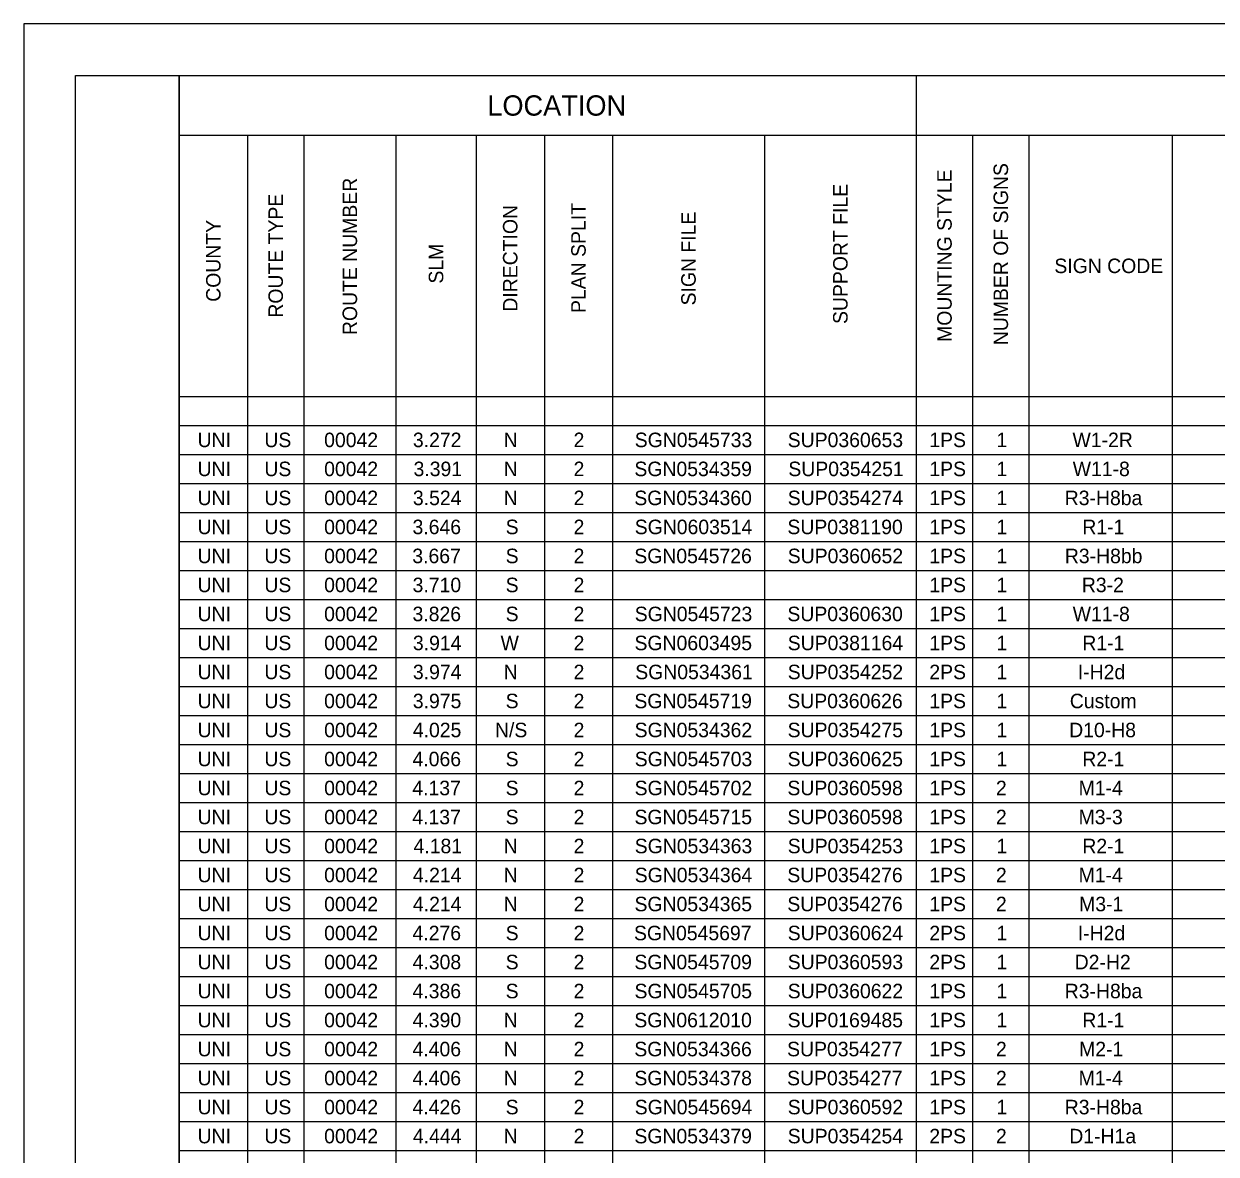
# Model space of a CAD drawing. Extents: x 0 to 34, y 0 to 22.
# Drawn here: x 0 to 11.51, y 11.09 to 22 of the extents above; entities that cross this region are included whole.
import ezdxf

# ---------------------------------------------------------------- set-up
doc = ezdxf.new("R2010")
doc.units = 0
for name, color, linetype in [('SH_Border', 7, 'Continuous'), ('SH_Cut_Line', 7, 'Continuous'), ('SH_Data', 7, 'Continuous'), ('SH_Text', 7, 'Continuous')]:
    doc.layers.add(name, color=color, linetype=linetype)

msp = doc.modelspace()

# ---------------------------------------------------------------- linework, layer by layer
at = {"layer": 'SH_Border'}
for points in [[(0.5, 21.5), (1.5, 21.5), (1.5, 0.5), (0.5, 0.5)], [(1.5, 21.5), (33.5, 21.5), (33.5, 0.5), (1.5, 0.5)]]:
    msp.add_lwpolyline(points, close=True, dxfattribs=at)
at = {"layer": 'SH_Cut_Line'}
msp.add_lwpolyline([(0, 0), (34, 0), (34, 22), (0, 22)], close=True, dxfattribs=at)
at = {"layer": 'SH_Data'}
for p, q in [((1.5, 21.5), (32.004, 21.5)), ((8.615, 21.5), (8.615, 0.764)), ((1.5, 20.924), (28.232, 20.924)), ((1.5, 20.924), (1.5, 0.764)), ((2.159, 20.924), (2.159, 0.764)), ((2.702, 20.924), (2.702, 0.764)), ((3.592, 20.924), (3.592, 0.764)), ((4.366, 20.924), (4.366, 0.764)), ((5.025, 20.924), (5.025, 0.764)), ((5.684, 20.924), (5.684, 0.764)), ((7.149, 20.924), (7.149, 0.764)), ((9.159, 20.924), (9.159, 0.764)), ((9.702, 20.924), (9.702, 0.764)), ((11.086, 20.924), (11.086, 0.764)), ((1.5, 18.404), (32.004, 18.404)), ((1.5, 18.124), (32.004, 18.124)), ((1.5, 17.844), (32.004, 17.844)), ((1.5, 17.564), (32.004, 17.564)), ((1.5, 17.284), (32.004, 17.284)), ((1.5, 17.004), (32.004, 17.004)), ((1.5, 16.724), (32.004, 16.724)), ((1.5, 16.444), (32.004, 16.444)), ((1.5, 16.164), (32.004, 16.164)), ((1.5, 15.884), (32.004, 15.884)), ((1.5, 15.604), (32.004, 15.604)), ((1.5, 15.324), (32.004, 15.324)), ((1.5, 15.044), (32.004, 15.044)), ((1.5, 14.764), (32.004, 14.764)), ((1.5, 14.484), (32.004, 14.484)), ((1.5, 14.204), (32.004, 14.204)), ((1.5, 13.924), (32.004, 13.924)), ((1.5, 13.644), (32.004, 13.644)), ((1.5, 13.364), (32.004, 13.364)), ((1.5, 13.084), (32.004, 13.084)), ((1.5, 12.804), (32.004, 12.804)), ((1.5, 12.524), (32.004, 12.524)), ((1.5, 12.244), (32.004, 12.244)), ((1.5, 11.964), (32.004, 11.964)), ((1.5, 11.684), (32.004, 11.684)), ((1.5, 11.404), (32.004, 11.404)), ((1.5, 11.124), (32.004, 11.124))]:
    msp.add_line(p, q, dxfattribs=at)

# ---------------------------------------------------------------- texts
at = {"layer": 'SH_Text'}
for s, height, p in [('LOCATION', 0.196, (4.474, 21.114)), ('SIGN CODE', 0.14, (9.948, 19.594)), ('UNI', 0.14, (1.677, 17.914)), ('US', 0.14, (2.322, 17.914)), ('00042', 0.14, (2.899, 17.914)), ('3.272', 0.14, (3.756, 17.914)), ('N', 0.14, (4.632, 17.914)), ('2', 0.14, (5.307, 17.914)), ('SGN0545733', 0.14, (5.897, 17.914)), ('SUP0360653', 0.14, (7.374, 17.914)), ('1PS', 0.14, (8.741, 17.914)), ('1', 0.14, (9.389, 17.914)), ('W1-2R', 0.14, (10.123, 17.914)), ('UNI', 0.14, (1.677, 17.634)), ('US', 0.14, (2.322, 17.634)), ('00042', 0.14, (2.899, 17.634)), ('3.391', 0.14, (3.762, 17.634)), ('N', 0.14, (4.632, 17.634)), ('2', 0.14, (5.307, 17.634)), ('SGN0534359', 0.14, (5.894, 17.634)), ('SUP0354251', 0.14, (7.38, 17.634)), ('1PS', 0.14, (8.741, 17.634)), ('1', 0.14, (9.389, 17.634)), ('W11-8', 0.14, (10.125, 17.634)), ('US', 0.14, (2.322, 17.354)), ('00042', 0.14, (2.899, 17.354)), ('3.524', 0.14, (3.756, 17.354)), ('2', 0.14, (5.307, 17.354)), ('SGN0534360', 0.14, (5.893, 17.354)), ('SUP0354274', 0.14, (7.374, 17.354)), ('1PS', 0.14, (8.741, 17.354)), ('R3-H8ba', 0.14, (10.048, 17.354)), ('UNI', 0.14, (1.677, 17.354)), ('N', 0.14, (4.632, 17.354)), ('1', 0.14, (9.389, 17.354)), ('UNI', 0.14, (1.677, 17.074)), ('US', 0.14, (2.322, 17.074)), ('00042', 0.14, (2.899, 17.074)), ('3.646', 0.14, (3.752, 17.074)), ('S', 0.14, (4.651, 17.074)), ('2', 0.14, (5.307, 17.074)), ('SGN0603514', 0.14, (5.897, 17.074)), ('SUP0381190', 0.14, (7.371, 17.074)), ('1PS', 0.14, (8.741, 17.074)), ('1', 0.14, (9.389, 17.074)), ('R1-1', 0.14, (10.218, 17.074)), ('UNI', 0.14, (1.677, 16.794)), ('US', 0.14, (2.322, 16.794)), ('00042', 0.14, (2.899, 16.794)), ('3.667', 0.14, (3.75, 16.794)), ('S', 0.14, (4.651, 16.794)), ('2', 0.14, (5.307, 16.794)), ('SGN0545726', 0.14, (5.893, 16.794)), ('SUP0360652', 0.14, (7.374, 16.794)), ('1PS', 0.14, (8.741, 16.794)), ('1', 0.14, (9.389, 16.794)), ('R3-H8bb', 0.14, (10.049, 16.794)), ('UNI', 0.14, (1.677, 16.514)), ('US', 0.14, (2.322, 16.514)), ('00042', 0.14, (2.899, 16.514)), ('3.710', 0.14, (3.753, 16.514)), ('S', 0.14, (4.651, 16.514)), ('2', 0.14, (5.307, 16.514)), ('1PS', 0.14, (8.741, 16.514)), ('1', 0.14, (9.389, 16.514)), ('R3-2', 0.14, (10.213, 16.514)), ('UNI', 0.14, (1.677, 16.234)), ('US', 0.14, (2.322, 16.234)), ('00042', 0.14, (2.899, 16.234)), ('3.826', 0.14, (3.752, 16.234)), ('S', 0.14, (4.651, 16.234)), ('2', 0.14, (5.307, 16.234)), ('SGN0545723', 0.14, (5.897, 16.234)), ('SUP0360630', 0.14, (7.371, 16.234)), ('1PS', 0.14, (8.741, 16.234)), ('1', 0.14, (9.389, 16.234)), ('W11-8', 0.14, (10.125, 16.234)), ('UNI', 0.14, (1.677, 15.954)), ('US', 0.14, (2.322, 15.954)), ('00042', 0.14, (2.899, 15.954)), ('3.914', 0.14, (3.756, 15.954)), ('W', 0.14, (4.602, 15.954)), ('2', 0.14, (5.307, 15.954)), ('SGN0603495', 0.14, (5.895, 15.954)), ('SUP0381164', 0.14, (7.374, 15.954)), ('1PS', 0.14, (8.741, 15.954)), ('1', 0.14, (9.389, 15.954)), ('R1-1', 0.14, (10.218, 15.954)), ('UNI', 0.14, (1.677, 15.674)), ('US', 0.14, (2.322, 15.674)), ('00042', 0.14, (2.899, 15.674)), ('3.974', 0.14, (3.756, 15.674)), ('N', 0.14, (4.632, 15.674)), ('2', 0.14, (5.307, 15.674)), ('SGN0534361', 0.14, (5.902, 15.674)), ('SUP0354252', 0.14, (7.374, 15.674)), ('2PS', 0.14, (8.741, 15.674)), ('1', 0.14, (9.389, 15.674)), ('I-H2d', 0.14, (10.174, 15.674)), ('UNI', 0.14, (1.677, 15.394)), ('US', 0.14, (2.322, 15.394)), ('00042', 0.14, (2.899, 15.394)), ('3.975', 0.14, (3.755, 15.394)), ('S', 0.14, (4.651, 15.394)), ('2', 0.14, (5.307, 15.394)), ('SGN0545719', 0.14, (5.894, 15.394)), ('SUP0360626', 0.14, (7.37, 15.394)), ('1PS', 0.14, (8.741, 15.394)), ('1', 0.14, (9.389, 15.394)), ('Custom', 0.14, (10.097, 15.394)), ('UNI', 0.14, (1.677, 15.114)), ('US', 0.14, (2.322, 15.114)), ('00042', 0.14, (2.899, 15.114)), ('4.025', 0.14, (3.755, 15.114)), ('N/S', 0.14, (4.548, 15.114)), ('2', 0.14, (5.307, 15.114)), ('SGN0534362', 0.14, (5.896, 15.114)), ('SUP0354275', 0.14, (7.373, 15.114)), ('1PS', 0.14, (8.741, 15.114)), ('1', 0.14, (9.389, 15.114)), ('D10-H8', 0.14, (10.091, 15.114)), ('UNI', 0.14, (1.677, 14.834)), ('US', 0.14, (2.322, 14.834)), ('00042', 0.14, (2.899, 14.834)), ('4.066', 0.14, (3.752, 14.834)), ('S', 0.14, (4.651, 14.834)), ('2', 0.14, (5.307, 14.834)), ('SGN0545703', 0.14, (5.897, 14.834)), ('SUP0360625', 0.14, (7.373, 14.834)), ('1PS', 0.14, (8.741, 14.834)), ('1', 0.14, (9.389, 14.834)), ('R2-1', 0.14, (10.218, 14.834)), ('UNI', 0.14, (1.677, 14.554)), ('US', 0.14, (2.322, 14.554)), ('00042', 0.14, (2.899, 14.554)), ('4.137', 0.14, (3.75, 14.554)), ('S', 0.14, (4.651, 14.554)), ('2', 0.14, (5.307, 14.554)), ('SGN0545702', 0.14, (5.896, 14.554)), ('SUP0360598', 0.14, (7.371, 14.554)), ('1PS', 0.14, (8.741, 14.554)), ('2', 0.14, (9.384, 14.554)), ('M1-4', 0.14, (10.182, 14.554)), ('UNI', 0.14, (1.677, 14.274)), ('US', 0.14, (2.322, 14.274)), ('00042', 0.14, (2.899, 14.274)), ('4.137', 0.14, (3.75, 14.274)), ('S', 0.14, (4.651, 14.274)), ('2', 0.14, (5.307, 14.274)), ('SGN0545715', 0.14, (5.895, 14.274)), ('SUP0360598', 0.14, (7.371, 14.274)), ('1PS', 0.14, (8.741, 14.274)), ('2', 0.14, (9.384, 14.274)), ('M3-3', 0.14, (10.182, 14.274)), ('UNI', 0.14, (1.677, 13.994)), ('US', 0.14, (2.322, 13.994)), ('00042', 0.14, (2.899, 13.994)), ('4.181', 0.14, (3.762, 13.994)), ('N', 0.14, (4.632, 13.994)), ('2', 0.14, (5.307, 13.994)), ('SGN0534363', 0.14, (5.897, 13.994)), ('SUP0354253', 0.14, (7.374, 13.994)), ('1PS', 0.14, (8.741, 13.994)), ('1', 0.14, (9.389, 13.994)), ('R2-1', 0.14, (10.218, 13.994)), ('UNI', 0.14, (1.677, 13.714)), ('US', 0.14, (2.322, 13.714)), ('00042', 0.14, (2.899, 13.714)), ('4.214', 0.14, (3.756, 13.714)), ('N', 0.14, (4.632, 13.714)), ('2', 0.14, (5.307, 13.714)), ('SGN0534364', 0.14, (5.897, 13.714)), ('SUP0354276', 0.14, (7.37, 13.714)), ('1PS', 0.14, (8.741, 13.714)), ('2', 0.14, (9.384, 13.714)), ('M1-4', 0.14, (10.182, 13.714)), ('UNI', 0.14, (1.677, 13.434)), ('US', 0.14, (2.322, 13.434)), ('00042', 0.14, (2.899, 13.434)), ('4.214', 0.14, (3.756, 13.434)), ('N', 0.14, (4.632, 13.434)), ('2', 0.14, (5.307, 13.434)), ('SGN0534365', 0.14, (5.895, 13.434)), ('SUP0354276', 0.14, (7.37, 13.434)), ('1PS', 0.14, (8.741, 13.434)), ('2', 0.14, (9.384, 13.434)), ('M3-1', 0.14, (10.187, 13.434)), ('UNI', 0.14, (1.677, 13.154)), ('US', 0.14, (2.322, 13.154)), ('00042', 0.14, (2.899, 13.154)), ('4.276', 0.14, (3.752, 13.154)), ('S', 0.14, (4.651, 13.154)), ('2', 0.14, (5.307, 13.154)), ('SGN0545697', 0.14, (5.89, 13.154)), ('SUP0360624', 0.14, (7.374, 13.154)), ('2PS', 0.14, (8.741, 13.154)), ('1', 0.14, (9.389, 13.154)), ('I-H2d', 0.14, (10.174, 13.154)), ('UNI', 0.14, (1.677, 12.874)), ('US', 0.14, (2.322, 12.874)), ('00042', 0.14, (2.899, 12.874)), ('4.308', 0.14, (3.753, 12.874)), ('S', 0.14, (4.651, 12.874)), ('2', 0.14, (5.307, 12.874)), ('SGN0545709', 0.14, (5.894, 12.874)), ('SUP0360593', 0.14, (7.374, 12.874)), ('2PS', 0.14, (8.741, 12.874)), ('1', 0.14, (9.389, 12.874)), ('D2-H2', 0.14, (10.144, 12.874)), ('UNI', 0.14, (1.677, 12.594)), ('US', 0.14, (2.322, 12.594)), ('00042', 0.14, (2.899, 12.594)), ('4.386', 0.14, (3.752, 12.594)), ('S', 0.14, (4.651, 12.594)), ('2', 0.14, (5.307, 12.594)), ('SGN0545705', 0.14, (5.895, 12.594)), ('SUP0360622', 0.14, (7.374, 12.594)), ('1PS', 0.14, (8.741, 12.594)), ('1', 0.14, (9.389, 12.594)), ('R3-H8ba', 0.14, (10.048, 12.594)), ('UNI', 0.14, (1.677, 12.314)), ('US', 0.14, (2.322, 12.314)), ('00042', 0.14, (2.899, 12.314)), ('4.390', 0.14, (3.753, 12.314)), ('N', 0.14, (4.632, 12.314)), ('2', 0.14, (5.307, 12.314)), ('SGN0612010', 0.14, (5.893, 12.314)), ('SUP0169485', 0.14, (7.373, 12.314)), ('1PS', 0.14, (8.741, 12.314)), ('1', 0.14, (9.389, 12.314)), ('R1-1', 0.14, (10.218, 12.314)), ('UNI', 0.14, (1.677, 12.034)), ('US', 0.14, (2.322, 12.034)), ('00042', 0.14, (2.899, 12.034)), ('4.406', 0.14, (3.752, 12.034)), ('N', 0.14, (4.632, 12.034)), ('2', 0.14, (5.307, 12.034)), ('SGN0534366', 0.14, (5.893, 12.034)), ('SUP0354277', 0.14, (7.368, 12.034)), ('1PS', 0.14, (8.741, 12.034)), ('2', 0.14, (9.384, 12.034)), ('M2-1', 0.14, (10.187, 12.034)), ('UNI', 0.14, (1.677, 11.754)), ('US', 0.14, (2.322, 11.754)), ('00042', 0.14, (2.899, 11.754)), ('4.406', 0.14, (3.752, 11.754)), ('N', 0.14, (4.632, 11.754)), ('2', 0.14, (5.307, 11.754)), ('SGN0534378', 0.14, (5.894, 11.754)), ('SUP0354277', 0.14, (7.368, 11.754)), ('1PS', 0.14, (8.741, 11.754)), ('2', 0.14, (9.384, 11.754)), ('M1-4', 0.14, (10.182, 11.754)), ('UNI', 0.14, (1.677, 11.474)), ('US', 0.14, (2.322, 11.474)), ('00042', 0.14, (2.899, 11.474)), ('4.426', 0.14, (3.752, 11.474)), ('S', 0.14, (4.651, 11.474)), ('2', 0.14, (5.307, 11.474)), ('SGN0545694', 0.14, (5.897, 11.474)), ('SUP0360592', 0.14, (7.374, 11.474)), ('1PS', 0.14, (8.741, 11.474)), ('1', 0.14, (9.389, 11.474)), ('R3-H8ba', 0.14, (10.048, 11.474)), ('UNI', 0.14, (1.677, 11.194)), ('US', 0.14, (2.322, 11.194)), ('00042', 0.14, (2.899, 11.194)), ('4.444', 0.14, (3.756, 11.194)), ('N', 0.14, (4.632, 11.194)), ('2', 0.14, (5.307, 11.194)), ('SGN0534379', 0.14, (5.894, 11.194)), ('SUP0354254', 0.14, (7.374, 11.194)), ('2PS', 0.14, (8.741, 11.194)), ('2', 0.14, (9.384, 11.194)), ('D1-H1a', 0.14, (10.092, 11.194))]:
    msp.add_text(s, height=height, dxfattribs=at).set_placement(p)
for s, p in [('NUMBER OF SIGNS', (9.501, 18.898)), ('ROUTE NUMBER', (3.217, 18.996)), ('MOUNTING STYLE', (8.957, 18.93)), ('SUPPORT FILE', (7.952, 19.103)), ('ROUTE TYPE', (2.501, 19.164)), ('PLAN SPLIT', (5.424, 19.209)), ('DIRECTION', (4.765, 19.222)), ('SIGN FILE', (6.486, 19.282)), ('COUNTY', (1.899, 19.317)), ('SLM', (4.049, 19.493))]:
    msp.add_text(s, height=0.14, rotation=90, dxfattribs=at).set_placement(p)

doc.saveas('drawing.dxf')
